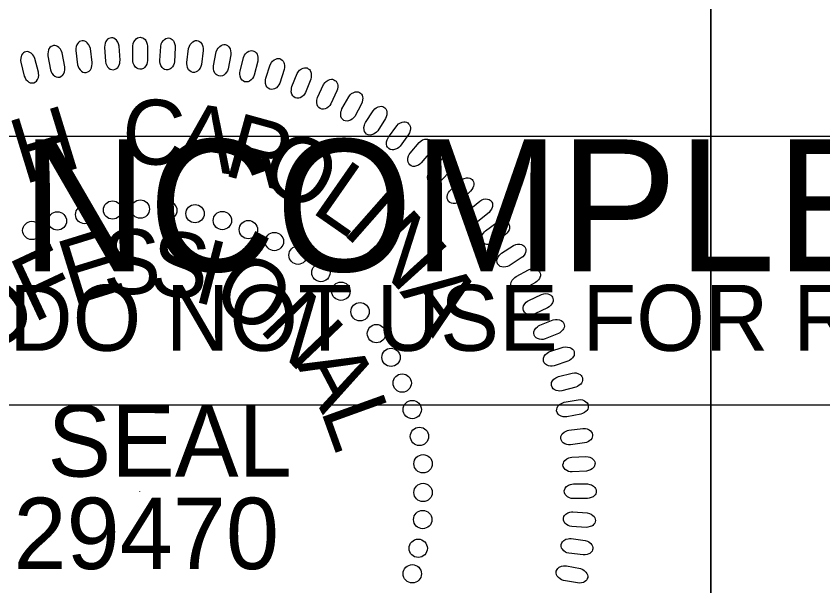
# Model space of a CAD drawing. Extents: x 497599 to 513368, y 404140 to 476034.
# Drawn here: x 507198 to 507268.5, y 439739.1 to 439788.9 of the extents above; entities that cross this region are included whole.
import ezdxf

# ---------------------------------------------------------------- set-up
doc = ezdxf.new("R2010")
doc.units = 0
for name, color, linetype in [('Sheet PE Seal Cell', 7, 'Continuous'), ('Sheet Profile CELL', 7, 'Continuous'), ('Sheet Sticker Incomplete CELL', 7, 'Continuous')]:
    doc.layers.add(name, color=color, linetype=linetype)

msp = doc.modelspace()

# ---------------------------------------------------------------- linework, layer by layer
at = {"layer": 'Sheet PE Seal Cell'}
msp.add_line((507208.804, 439747.402), (507208.804, 439747.355), dxfattribs=at)
for points in [[(507204.659, 439784.876), (507204.505, 439786.093), (507204.441, 439786.306), (507204.372, 439786.438), (507204.239, 439786.592), (507204.129, 439786.689), (507204.008, 439786.754), (507203.899, 439786.78), (507203.785, 439786.786), (507203.676, 439786.752), (507203.562, 439786.708), (507203.465, 439786.635), (507203.374, 439786.523), (507203.325, 439786.437), (507203.276, 439786.28), (507203.239, 439786.094), (507203.237, 439785.933), (507203.387, 439784.686), (507203.43, 439784.52), (507203.492, 439784.387), (507203.601, 439784.24), (507203.73, 439784.115), (507203.836, 439784.049), (507203.999, 439784.008), (507204.15, 439784.007), (507204.294, 439784.066), (507204.391, 439784.128), (507204.505, 439784.243), (507204.602, 439784.426), (507204.646, 439784.613), (507204.66, 439784.745)], [(507207.097, 439785.078), (507207.02, 439786.303), (507206.969, 439786.519), (507206.909, 439786.655), (507206.786, 439786.818), (507206.682, 439786.921), (507206.565, 439786.994), (507206.459, 439787.027), (507206.345, 439787.04), (507206.235, 439787.013), (507206.117, 439786.976), (507206.016, 439786.91), (507205.918, 439786.803), (507205.864, 439786.72), (507205.805, 439786.566), (507205.757, 439786.383), (507205.745, 439786.223), (507205.816, 439784.968), (507205.849, 439784.801), (507205.902, 439784.664), (507206.001, 439784.51), (507206.123, 439784.378), (507206.224, 439784.304), (507206.385, 439784.254), (507206.535, 439784.244), (507206.682, 439784.293), (507206.783, 439784.35), (507206.904, 439784.457), (507207.013, 439784.633), (507207.068, 439784.817), (507207.091, 439784.948)], [(507208.212, 439785.087), (507208.213, 439786.314), (507208.25, 439786.533), (507208.303, 439786.674), (507208.415, 439786.843), (507208.512, 439786.952), (507208.624, 439787.032), (507208.729, 439787.072), (507208.841, 439787.092), (507208.953, 439787.072), (507209.073, 439787.042), (507209.177, 439786.982), (507209.282, 439786.882), (507209.342, 439786.802), (507209.409, 439786.653), (507209.469, 439786.473), (507209.491, 439786.313), (507209.498, 439785.057), (507209.476, 439784.887), (507209.431, 439784.748), (507209.341, 439784.589), (507209.229, 439784.448), (507209.132, 439784.369), (507208.974, 439784.309), (507208.825, 439784.29), (507208.676, 439784.329), (507208.571, 439784.379), (507208.444, 439784.479), (507208.324, 439784.649), (507208.257, 439784.828), (507208.227, 439784.958)], [(507210.572, 439785.061), (507210.649, 439786.285), (507210.7, 439786.502), (507210.761, 439786.638), (507210.884, 439786.8), (507210.987, 439786.903), (507211.105, 439786.976), (507211.212, 439787.009), (507211.325, 439787.022), (507211.435, 439786.994), (507211.553, 439786.957), (507211.654, 439786.891), (507211.752, 439786.785), (507211.806, 439786.702), (507211.864, 439786.548), (507211.912, 439786.365), (507211.925, 439786.205), (507211.853, 439784.95), (507211.82, 439784.782), (507211.766, 439784.646), (507211.666, 439784.492), (507211.546, 439784.36), (507211.444, 439784.286), (507211.283, 439784.236), (507211.133, 439784.226), (507210.986, 439784.275), (507210.885, 439784.332), (507210.764, 439784.439), (507210.656, 439784.616), (507210.6, 439784.799), (507210.578, 439784.931)], [(507212.934, 439784.886), (507213.088, 439786.103), (507213.153, 439786.316), (507213.222, 439786.447), (507213.355, 439786.602), (507213.465, 439786.699), (507213.587, 439786.763), (507213.695, 439786.79), (507213.809, 439786.796), (507213.918, 439786.761), (507214.032, 439786.717), (507214.129, 439786.644), (507214.22, 439786.532), (507214.269, 439786.446), (507214.318, 439786.289), (507214.354, 439786.103), (507214.356, 439785.942), (507214.206, 439784.694), (507214.162, 439784.529), (507214.1, 439784.396), (507213.991, 439784.249), (507213.862, 439784.125), (507213.756, 439784.058), (507213.593, 439784.018), (507213.442, 439784.017), (507213.298, 439784.076), (507213.201, 439784.138), (507213.087, 439784.253), (507212.99, 439784.436), (507212.946, 439784.623), (507212.933, 439784.756)], [(507202.278, 439784.508), (507202.048, 439785.712), (507201.97, 439785.921), (507201.893, 439786.049), (507201.751, 439786.194), (507201.635, 439786.283), (507201.51, 439786.341), (507201.4, 439786.361), (507201.286, 439786.36), (507201.179, 439786.319), (507201.068, 439786.267), (507200.976, 439786.189), (507200.891, 439786.071), (507200.848, 439785.981), (507200.81, 439785.822), (507200.785, 439785.635), (507200.792, 439785.474), (507201.02, 439784.238), (507201.074, 439784.075), (507201.144, 439783.946), (507201.262, 439783.807), (507201.399, 439783.69), (507201.509, 439783.63), (507201.674, 439783.601), (507201.825, 439783.61), (507201.964, 439783.677), (507202.058, 439783.745), (507202.164, 439783.867), (507202.25, 439784.055), (507202.282, 439784.244), (507202.287, 439784.377)], [(507215.273, 439784.599), (507215.504, 439785.804), (507215.582, 439786.013), (507215.659, 439786.14), (507215.801, 439786.285), (507215.917, 439786.375), (507216.042, 439786.432), (507216.152, 439786.452), (507216.267, 439786.451), (507216.373, 439786.41), (507216.485, 439786.358), (507216.576, 439786.279), (507216.66, 439786.162), (507216.704, 439786.072), (507216.742, 439785.913), (507216.767, 439785.725), (507216.759, 439785.564), (507216.531, 439784.328), (507216.476, 439784.166), (507216.406, 439784.038), (507216.288, 439783.897), (507216.152, 439783.781), (507216.042, 439783.721), (507215.876, 439783.692), (507215.726, 439783.701), (507215.586, 439783.768), (507215.493, 439783.836), (507215.387, 439783.958), (507215.301, 439784.147), (507215.269, 439784.336), (507215.264, 439784.469)], [(507199.972, 439784.035), (507199.668, 439785.224), (507199.577, 439785.427), (507199.492, 439785.55), (507199.341, 439785.686), (507199.219, 439785.768), (507199.091, 439785.817), (507198.979, 439785.83), (507198.866, 439785.821), (507198.762, 439785.775), (507198.654, 439785.715), (507198.568, 439785.632), (507198.491, 439785.509), (507198.453, 439785.417), (507198.425, 439785.255), (507198.412, 439785.067), (507198.429, 439784.907), (507198.734, 439783.687), (507198.798, 439783.529), (507198.876, 439783.405), (507199.003, 439783.272), (507199.146, 439783.165), (507199.26, 439783.112), (507199.427, 439783.092), (507199.577, 439783.111), (507199.712, 439783.186), (507199.801, 439783.26), (507199.899, 439783.389), (507199.972, 439783.583), (507199.993, 439783.773), (507199.99, 439783.906)], [(507217.579, 439784.125), (507217.884, 439785.313), (507217.975, 439785.516), (507218.06, 439785.639), (507218.211, 439785.776), (507218.332, 439785.857), (507218.461, 439785.907), (507218.572, 439785.919), (507218.686, 439785.911), (507218.789, 439785.864), (507218.898, 439785.805), (507218.984, 439785.721), (507219.06, 439785.598), (507219.099, 439785.506), (507219.127, 439785.344), (507219.14, 439785.155), (507219.123, 439784.995), (507218.816, 439783.776), (507218.752, 439783.618), (507218.674, 439783.494), (507218.547, 439783.362), (507218.404, 439783.254), (507218.29, 439783.201), (507218.123, 439783.182), (507217.974, 439783.2), (507217.839, 439783.276), (507217.75, 439783.35), (507217.652, 439783.479), (507217.578, 439783.673), (507217.558, 439783.863), (507217.561, 439783.996)], [(507219.828, 439783.503), (507220.208, 439784.67), (507220.312, 439784.867), (507220.404, 439784.983), (507220.564, 439785.11), (507220.69, 439785.184), (507220.821, 439785.226), (507220.933, 439785.231), (507221.046, 439785.216), (507221.146, 439785.162), (507221.251, 439785.096), (507221.332, 439785.007), (507221.4, 439784.88), (507221.432, 439784.786), (507221.45, 439784.622), (507221.452, 439784.433), (507221.424, 439784.275), (507221.042, 439783.078), (507220.969, 439782.923), (507220.882, 439782.804), (507220.748, 439782.68), (507220.598, 439782.582), (507220.481, 439782.536), (507220.313, 439782.528), (507220.164, 439782.556), (507220.035, 439782.639), (507219.951, 439782.719), (507219.861, 439782.853), (507219.8, 439783.051), (507219.791, 439783.243), (507219.803, 439783.376)], [(507222.112, 439782.769), (507222.564, 439783.909), (507222.68, 439784.099), (507222.779, 439784.21), (507222.946, 439784.326), (507223.077, 439784.392), (507223.211, 439784.425), (507223.323, 439784.423), (507223.434, 439784.401), (507223.531, 439784.341), (507223.631, 439784.269), (507223.706, 439784.175), (507223.767, 439784.043), (507223.793, 439783.947), (507223.801, 439783.784), (507223.791, 439783.595), (507223.752, 439783.438), (507223.296, 439782.267), (507223.212, 439782.118), (507223.12, 439782.004), (507222.978, 439781.89), (507222.822, 439781.8), (507222.702, 439781.762), (507222.534, 439781.765), (507222.388, 439781.801), (507222.264, 439781.893), (507222.184, 439781.978), (507222.103, 439782.118), (507222.055, 439782.32), (507222.058, 439782.511), (507222.078, 439782.643)], [(507224.353, 439781.835), (507224.876, 439782.944), (507225.003, 439783.127), (507225.11, 439783.231), (507225.284, 439783.337), (507225.418, 439783.395), (507225.554, 439783.418), (507225.665, 439783.41), (507225.775, 439783.38), (507225.868, 439783.314), (507225.964, 439783.237), (507226.033, 439783.138), (507226.085, 439783.003), (507226.105, 439782.906), (507226.102, 439782.741), (507226.08, 439782.554), (507226.033, 439782.399), (507225.504, 439781.259), (507225.411, 439781.116), (507225.311, 439781.008), (507225.162, 439780.902), (507225.001, 439780.824), (507224.879, 439780.793), (507224.711, 439780.805), (507224.568, 439780.852), (507224.45, 439780.951), (507224.376, 439781.041), (507224.304, 439781.185), (507224.268, 439781.389), (507224.283, 439781.581), (507224.312, 439781.71)], [(507226.477, 439780.819), (507227.068, 439781.894), (507227.207, 439782.068), (507227.32, 439782.165), (507227.5, 439782.259), (507227.638, 439782.309), (507227.775, 439782.325), (507227.886, 439782.309), (507227.994, 439782.273), (507228.082, 439782.201), (507228.172, 439782.117), (507228.235, 439782.015), (507228.279, 439781.877), (507228.293, 439781.778), (507228.28, 439781.615), (507228.245, 439781.428), (507228.189, 439781.278), (507227.589, 439780.173), (507227.488, 439780.036), (507227.381, 439779.935), (507227.226, 439779.838), (507227.06, 439779.77), (507226.937, 439779.747), (507226.77, 439779.77), (507226.63, 439779.825), (507226.518, 439779.931), (507226.45, 439780.026), (507226.387, 439780.175), (507226.364, 439780.381), (507226.391, 439780.57), (507226.428, 439780.699)], [(507228.535, 439779.634), (507229.193, 439780.67), (507229.342, 439780.835), (507229.461, 439780.924), (507229.646, 439781.008), (507229.788, 439781.049), (507229.925, 439781.056), (507230.034, 439781.033), (507230.14, 439780.989), (507230.224, 439780.913), (507230.308, 439780.823), (507230.365, 439780.717), (507230.4, 439780.576), (507230.407, 439780.477), (507230.384, 439780.314), (507230.339, 439780.131), (507230.272, 439779.984), (507229.605, 439778.92), (507229.494, 439778.789), (507229.382, 439778.695), (507229.221, 439778.608), (507229.052, 439778.55), (507228.926, 439778.535), (507228.761, 439778.568), (507228.625, 439778.632), (507228.52, 439778.746), (507228.459, 439778.844), (507228.404, 439778.997), (507228.395, 439779.203), (507228.434, 439779.391), (507228.479, 439779.517)], [(507230.535, 439778.361), (507231.256, 439779.353), (507231.416, 439779.509), (507231.54, 439779.591), (507231.73, 439779.662), (507231.873, 439779.694), (507232.011, 439779.693), (507232.12, 439779.663), (507232.222, 439779.613), (507232.301, 439779.532), (507232.38, 439779.437), (507232.429, 439779.327), (507232.455, 439779.185), (507232.457, 439779.085), (507232.423, 439778.924), (507232.366, 439778.744), (507232.29, 439778.602), (507231.557, 439777.581), (507231.439, 439777.457), (507231.321, 439777.37), (507231.155, 439777.294), (507230.982, 439777.247), (507230.856, 439777.24), (507230.694, 439777.284), (507230.562, 439777.356), (507230.464, 439777.476), (507230.409, 439777.578), (507230.365, 439777.733), (507230.368, 439777.94), (507230.419, 439778.125), (507230.471, 439778.248)], [(507232.43, 439776.945), (507233.212, 439777.89), (507233.38, 439778.035), (507233.51, 439778.109), (507233.704, 439778.169), (507233.849, 439778.191), (507233.986, 439778.181), (507234.092, 439778.145), (507234.192, 439778.088), (507234.265, 439778.002), (507234.338, 439777.902), (507234.381, 439777.79), (507234.398, 439777.646), (507234.393, 439777.547), (507234.349, 439777.388), (507234.281, 439777.212), (507234.197, 439777.075), (507233.401, 439776.102), (507233.275, 439775.985), (507233.152, 439775.907), (507232.981, 439775.841), (507232.805, 439775.805), (507232.68, 439775.805), (507232.521, 439775.859), (507232.393, 439775.94), (507232.303, 439776.065), (507232.254, 439776.171), (507232.22, 439776.328), (507232.236, 439776.535), (507232.299, 439776.717), (507232.359, 439776.835)], [(507234.201, 439775.431), (507235.041, 439776.325), (507235.219, 439776.459), (507235.352, 439776.525), (507235.55, 439776.572), (507235.696, 439776.585), (507235.832, 439776.567), (507235.936, 439776.524), (507236.032, 439776.462), (507236.1, 439776.371), (507236.166, 439776.267), (507236.202, 439776.152), (507236.21, 439776.007), (507236.199, 439775.908), (507236.145, 439775.753), (507236.066, 439775.581), (507235.973, 439775.45), (507235.118, 439774.529), (507234.985, 439774.421), (507234.857, 439774.35), (507234.682, 439774.295), (507234.506, 439774.27), (507234.379, 439774.278), (507234.224, 439774.342), (507234.101, 439774.43), (507234.02, 439774.561), (507233.978, 439774.669), (507233.954, 439774.829), (507233.983, 439775.034), (507234.056, 439775.211), (507234.124, 439775.326)], [(507235.946, 439773.737), (507236.84, 439774.577), (507237.026, 439774.699), (507237.163, 439774.757), (507237.363, 439774.791), (507237.51, 439774.796), (507237.645, 439774.769), (507237.746, 439774.72), (507237.837, 439774.651), (507237.899, 439774.556), (507237.959, 439774.448), (507237.987, 439774.331), (507237.986, 439774.186), (507237.969, 439774.088), (507237.906, 439773.937), (507237.816, 439773.77), (507237.715, 439773.644), (507236.803, 439772.78), (507236.665, 439772.68), (507236.532, 439772.617), (507236.355, 439772.573), (507236.176, 439772.559), (507236.051, 439772.575), (507235.9, 439772.649), (507235.783, 439772.745), (507235.71, 439772.88), (507235.675, 439772.991), (507235.66, 439773.152), (507235.702, 439773.355), (507235.787, 439773.528), (507235.862, 439773.638)], [(507237.557, 439771.991), (507238.503, 439772.773), (507238.696, 439772.883), (507238.837, 439772.932), (507239.039, 439772.954), (507239.186, 439772.949), (507239.319, 439772.913), (507239.416, 439772.858), (507239.503, 439772.784), (507239.559, 439772.685), (507239.612, 439772.574), (507239.633, 439772.455), (507239.622, 439772.311), (507239.599, 439772.214), (507239.526, 439772.067), (507239.426, 439771.907), (507239.318, 439771.787), (507238.354, 439770.981), (507238.209, 439770.89), (507238.073, 439770.836), (507237.893, 439770.804), (507237.713, 439770.801), (507237.59, 439770.825), (507237.443, 439770.907), (507237.333, 439771.01), (507237.269, 439771.151), (507237.24, 439771.263), (507237.236, 439771.425), (507237.291, 439771.625), (507237.386, 439771.791), (507237.467, 439771.897)], [(507239.018, 439770.169), (507240.011, 439770.889), (507240.21, 439770.988), (507240.354, 439771.028), (507240.557, 439771.037), (507240.703, 439771.022), (507240.833, 439770.979), (507240.927, 439770.917), (507241.009, 439770.838), (507241.059, 439770.735), (507241.105, 439770.622), (507241.118, 439770.502), (507241.098, 439770.358), (507241.069, 439770.263), (507240.987, 439770.12), (507240.877, 439769.967), (507240.762, 439769.855), (507239.749, 439769.11), (507239.599, 439769.029), (507239.459, 439768.983), (507239.278, 439768.962), (507239.098, 439768.971), (507238.977, 439769.003), (507238.836, 439769.094), (507238.732, 439769.204), (507238.677, 439769.348), (507238.656, 439769.462), (507238.661, 439769.624), (507238.729, 439769.82), (507238.834, 439769.98), (507238.922, 439770.08)], [(507240.418, 439768.222), (507241.454, 439768.88), (507241.66, 439768.966), (507241.806, 439768.996), (507242.009, 439768.993), (507242.154, 439768.969), (507242.281, 439768.917), (507242.371, 439768.85), (507242.448, 439768.766), (507242.491, 439768.661), (507242.53, 439768.544), (507242.535, 439768.423), (507242.507, 439768.281), (507242.472, 439768.188), (507242.381, 439768.051), (507242.262, 439767.905), (507242.139, 439767.8), (507241.082, 439767.121), (507240.927, 439767.049), (507240.785, 439767.013), (507240.602, 439767.003), (507240.424, 439767.022), (507240.304, 439767.062), (507240.17, 439767.162), (507240.073, 439767.278), (507240.027, 439767.425), (507240.013, 439767.54), (507240.029, 439767.702), (507240.108, 439767.893), (507240.224, 439768.046), (507240.317, 439768.141)], [(507241.679, 439766.173), (507242.755, 439766.763), (507242.965, 439766.836), (507243.112, 439766.858), (507243.315, 439766.842), (507243.458, 439766.809), (507243.582, 439766.748), (507243.667, 439766.676), (507243.739, 439766.588), (507243.775, 439766.48), (507243.806, 439766.36), (507243.805, 439766.24), (507243.768, 439766.1), (507243.726, 439766.01), (507243.628, 439765.878), (507243.499, 439765.74), (507243.37, 439765.643), (507242.272, 439765.032), (507242.113, 439764.97), (507241.968, 439764.942), (507241.786, 439764.944), (507241.61, 439764.974), (507241.492, 439765.021), (507241.365, 439765.13), (507241.275, 439765.251), (507241.238, 439765.401), (507241.231, 439765.517), (507241.258, 439765.677), (507241.349, 439765.863), (507241.474, 439766.009), (507241.573, 439766.098)], [(507242.787, 439764.09), (507243.897, 439764.612), (507244.111, 439764.671), (507244.26, 439764.684), (507244.461, 439764.654), (507244.602, 439764.612), (507244.722, 439764.545), (507244.802, 439764.467), (507244.868, 439764.374), (507244.898, 439764.264), (507244.921, 439764.143), (507244.912, 439764.023), (507244.866, 439763.886), (507244.819, 439763.798), (507244.712, 439763.673), (507244.575, 439763.543), (507244.44, 439763.455), (507243.306, 439762.913), (507243.144, 439762.862), (507242.998, 439762.843), (507242.816, 439762.856), (507242.642, 439762.898), (507242.528, 439762.952), (507242.407, 439763.069), (507242.325, 439763.196), (507242.298, 439763.348), (507242.299, 439763.464), (507242.334, 439763.622), (507242.438, 439763.802), (507242.571, 439763.939), (507242.676, 439764.021)], [(507243.766, 439761.928), (507244.907, 439762.38), (507245.125, 439762.425), (507245.274, 439762.429), (507245.472, 439762.387), (507245.61, 439762.336), (507245.726, 439762.261), (507245.801, 439762.179), (507245.861, 439762.082), (507245.883, 439761.97), (507245.9, 439761.848), (507245.883, 439761.729), (507245.828, 439761.595), (507245.777, 439761.51), (507245.662, 439761.392), (507245.517, 439761.27), (507245.377, 439761.191), (507244.211, 439760.722), (507244.046, 439760.68), (507243.899, 439760.671), (507243.718, 439760.696), (507243.547, 439760.748), (507243.436, 439760.809), (507243.323, 439760.934), (507243.25, 439761.065), (507243.232, 439761.219), (507243.24, 439761.335), (507243.285, 439761.49), (507243.4, 439761.663), (507243.542, 439761.792), (507243.652, 439761.867)], [(507244.64, 439759.614), (507245.808, 439759.993), (507246.028, 439760.025), (507246.177, 439760.019), (507246.372, 439759.964), (507246.507, 439759.906), (507246.617, 439759.824), (507246.687, 439759.737), (507246.741, 439759.636), (507246.757, 439759.523), (507246.765, 439759.4), (507246.741, 439759.283), (507246.678, 439759.152), (507246.621, 439759.07), (507246.499, 439758.959), (507246.347, 439758.848), (507246.202, 439758.777), (507245.009, 439758.382), (507244.841, 439758.351), (507244.694, 439758.351), (507244.515, 439758.387), (507244.348, 439758.45), (507244.241, 439758.518), (507244.135, 439758.649), (507244.071, 439758.785), (507244.063, 439758.94), (507244.078, 439759.054), (507244.133, 439759.206), (507244.257, 439759.372), (507244.408, 439759.492), (507244.522, 439759.56)], [(507245.385, 439757.441), (507246.573, 439757.745), (507246.795, 439757.764), (507246.943, 439757.748), (507247.136, 439757.682), (507247.266, 439757.615), (507247.371, 439757.526), (507247.436, 439757.435), (507247.483, 439757.331), (507247.492, 439757.217), (507247.492, 439757.094), (507247.461, 439756.978), (507247.39, 439756.852), (507247.327, 439756.774), (507247.199, 439756.672), (507247.04, 439756.569), (507246.891, 439756.508), (507245.676, 439756.189), (507245.506, 439756.168), (507245.359, 439756.177), (507245.182, 439756.224), (507245.02, 439756.298), (507244.918, 439756.372), (507244.821, 439756.509), (507244.765, 439756.649), (507244.766, 439756.804), (507244.788, 439756.917), (507244.854, 439757.066), (507244.988, 439757.223), (507245.145, 439757.333), (507245.264, 439757.394)], [(507245.895, 439755.187), (507247.1, 439755.416), (507247.322, 439755.42), (507247.469, 439755.396), (507247.657, 439755.317), (507247.783, 439755.242), (507247.883, 439755.147), (507247.941, 439755.052), (507247.982, 439754.945), (507247.983, 439754.832), (507247.975, 439754.708), (507247.937, 439754.595), (507247.858, 439754.473), (507247.791, 439754.399), (507247.656, 439754.305), (507247.491, 439754.213), (507247.339, 439754.161), (507246.106, 439753.918), (507245.935, 439753.909), (507245.79, 439753.927), (507245.616, 439753.985), (507245.458, 439754.069), (507245.362, 439754.149), (507245.273, 439754.293), (507245.226, 439754.436), (507245.237, 439754.59), (507245.266, 439754.702), (507245.34, 439754.846), (507245.485, 439754.994), (507245.649, 439755.095), (507245.77, 439755.148)], [(507246.293, 439752.748), (507247.51, 439752.901), (507247.732, 439752.891), (507247.878, 439752.857), (507248.06, 439752.767), (507248.181, 439752.684), (507248.274, 439752.583), (507248.327, 439752.485), (507248.36, 439752.376), (507248.355, 439752.262), (507248.34, 439752.139), (507248.294, 439752.028), (507248.208, 439751.912), (507248.136, 439751.843), (507247.996, 439751.757), (507247.825, 439751.675), (507247.67, 439751.633), (507246.424, 439751.468), (507246.253, 439751.47), (507246.109, 439751.497), (507245.94, 439751.566), (507245.787, 439751.659), (507245.696, 439751.746), (507245.616, 439751.894), (507245.578, 439752.04), (507245.599, 439752.193), (507245.636, 439752.303), (507245.719, 439752.442), (507245.872, 439752.582), (507246.042, 439752.671), (507246.167, 439752.716)], [(507246.537, 439750.383), (507247.761, 439750.459), (507247.982, 439750.435), (507248.125, 439750.393), (507248.301, 439750.291), (507248.416, 439750.201), (507248.503, 439750.094), (507248.549, 439749.992), (507248.576, 439749.881), (507248.563, 439749.768), (507248.541, 439749.647), (507248.488, 439749.539), (507248.395, 439749.428), (507248.319, 439749.364), (507248.174, 439749.287), (507247.998, 439749.216), (507247.841, 439749.184), (507246.587, 439749.098), (507246.416, 439749.11), (507246.274, 439749.146), (507246.109, 439749.225), (507245.963, 439749.328), (507245.877, 439749.42), (507245.808, 439749.573), (507245.778, 439749.722), (507245.809, 439749.873), (507245.852, 439749.981), (507245.944, 439750.114), (507246.105, 439750.243), (507246.281, 439750.322), (507246.408, 439750.36)], [(507246.686, 439748.053), (507247.913, 439748.052), (507248.132, 439748.015), (507248.271, 439747.962), (507248.441, 439747.85), (507248.551, 439747.753), (507248.63, 439747.641), (507248.67, 439747.537), (507248.69, 439747.424), (507248.67, 439747.312), (507248.64, 439747.192), (507248.58, 439747.088), (507248.48, 439746.983), (507248.401, 439746.923), (507248.251, 439746.856), (507248.071, 439746.796), (507247.912, 439746.774), (507246.655, 439746.767), (507246.486, 439746.789), (507246.346, 439746.835), (507246.186, 439746.924), (507246.047, 439747.036), (507245.967, 439747.133), (507245.907, 439747.29), (507245.888, 439747.44), (507245.928, 439747.59), (507245.978, 439747.694), (507246.077, 439747.821), (507246.247, 439747.94), (507246.426, 439748.008), (507246.556, 439748.038)], [(507246.653, 439745.612), (507247.877, 439745.535), (507248.093, 439745.483), (507248.229, 439745.423), (507248.392, 439745.3), (507248.495, 439745.196), (507248.567, 439745.079), (507248.601, 439744.973), (507248.613, 439744.858), (507248.586, 439744.748), (507248.549, 439744.631), (507248.483, 439744.53), (507248.377, 439744.432), (507248.293, 439744.378), (507248.139, 439744.32), (507247.957, 439744.271), (507247.796, 439744.259), (507246.541, 439744.331), (507246.374, 439744.364), (507246.237, 439744.418), (507246.084, 439744.517), (507245.952, 439744.638), (507245.878, 439744.74), (507245.828, 439744.9), (507245.818, 439745.051), (507245.867, 439745.198), (507245.923, 439745.299), (507246.031, 439745.419), (507246.207, 439745.528), (507246.391, 439745.584), (507246.522, 439745.605)], [(507246.486, 439743.272), (507247.703, 439743.118), (507247.916, 439743.053), (507248.048, 439742.984), (507248.203, 439742.852), (507248.299, 439742.741), (507248.364, 439742.62), (507248.39, 439742.512), (507248.396, 439742.397), (507248.362, 439742.289), (507248.317, 439742.174), (507248.245, 439742.078), (507248.133, 439741.986), (507248.047, 439741.937), (507247.889, 439741.889), (507247.704, 439741.852), (507247.543, 439741.85), (507246.295, 439742.001), (507246.129, 439742.044), (507245.997, 439742.106), (507245.85, 439742.215), (507245.725, 439742.344), (507245.658, 439742.45), (507245.619, 439742.614), (507245.618, 439742.764), (507245.676, 439742.908), (507245.739, 439743.005), (507245.853, 439743.119), (507246.037, 439743.216), (507246.224, 439743.261), (507246.356, 439743.273)], [(507246.089, 439740.885), (507247.294, 439740.654), (507247.502, 439740.577), (507247.63, 439740.5), (507247.776, 439740.357), (507247.865, 439740.241), (507247.922, 439740.116), (507247.942, 439740.006), (507247.94, 439739.892), (507247.9, 439739.786), (507247.848, 439739.674), (507247.769, 439739.582), (507247.651, 439739.499), (507247.562, 439739.454), (507247.403, 439739.416), (507247.215, 439739.391), (507247.054, 439739.399), (507245.819, 439739.628), (507245.656, 439739.682), (507245.528, 439739.752), (507245.388, 439739.87), (507245.271, 439740.006), (507245.211, 439740.117), (507245.182, 439740.282), (507245.191, 439740.433), (507245.258, 439740.572), (507245.326, 439740.666), (507245.448, 439740.772), (507245.637, 439740.857), (507245.827, 439740.89), (507245.959, 439740.894)]]:
    msp.add_lwpolyline(points, close=True, dxfattribs=at)
for centre in [(507206.441, 439771.992), (507208.869, 439772.071), (507211.258, 439771.95), (507204.012, 439771.594), (507213.647, 439771.671), (507216.035, 439771.072), (507201.623, 439771.037), (507199.393, 439770.201), (507218.304, 439770.275), (507220.573, 439769.238), (507222.643, 439768.043), (507224.634, 439766.528), (507226.385, 439764.894), (507228.056, 439763.101), (507229.489, 439761.188), (507230.762, 439759.116), (507231.735, 439756.867), (507232.61, 439754.556), (507233.246, 439752.206), (507233.564, 439749.815), (507233.563, 439747.306), (507233.533, 439744.942), (507233.134, 439742.432), (507232.616, 439740.201)]:
    msp.add_circle(centre, 0.801, dxfattribs=at)
at = {"layer": 'Sheet Profile CELL'}
msp.add_line((507258.678, 439811.094), (507258.678, 439698.644), dxfattribs=at)
for points in [[(507158.628, 439811.094), (507258.678, 439811.094), (507258.678, 439698.594), (507158.628, 439698.594)], [(507258.678, 439811.094), (507358.678, 439811.094), (507358.678, 439698.594), (507258.678, 439698.594)]]:
    msp.add_lwpolyline(points, close=True, dxfattribs=at)
at = {"layer": 'Sheet Sticker Incomplete CELL'}
msp.add_lwpolyline([(507185.195, 439754.938), (507185.195, 439778.438), (507332.195, 439778.438), (507332.195, 439754.938)], close=True, dxfattribs=at)

# ---------------------------------------------------------------- texts
at = {"layer": 'Sheet PE Seal Cell'}
for s, height, rotation, p in [('C', 5.669, 357.58768, (507207.187, 439776.082)), ('H', 5.669, 17.05575, (507198.682, 439774.198)), ('A', 5.669, 351.09832, (507211.763, 439775.874)), ('R', 5.669, 344.60896, (507215.969, 439775.079)), ('O', 5.669, 331.63025, (507218.924, 439774.425)), ('L', 5.669, 325.14089, (507223.657, 439771.894)), ('I', 5.669, 318.65154, (507226.35, 439770.041)), ('N', 5.669, 312.16218, (507228.155, 439768.621)), ('E', 5.669, 17.16862, (507202.878, 439763.629)), ('S', 5.669, 1.28903, (507205.646, 439764.589)), ('S', 5.669, 353.34923, (507209.506, 439764.69)), ('F', 5.669, 25.10842, (507199.488, 439762.091)), ('I', 5.669, 345.40944, (507213.307, 439764.059)), ('O', 5.669, 329.52984, (507214.81, 439763.887)), ('A', 5.669, 305.67282, (507231.475, 439764.841)), ('O', 5.669, 40.98802, (507195.791, 439758.952)), ('N', 5.669, 313.65025, (507219.122, 439761.583)), ('A', 5.669, 297.77065, (507222.459, 439758.502)), ('L', 5.669, 289.83086, (507224.583, 439754.507)), ('SEAL', 6.2363, 359.98136, (507200.762, 439748.695)), ('29470', 6.2363, 359.98136, (507197.791, 439740.617))]:
    msp.add_text(s, height=height, rotation=rotation, dxfattribs=at).set_placement(p)
at = {"layer": 'Sheet Sticker Incomplete CELL'}
for s, height, p in [('INCOMPLETE PLANS', 11.52, (507194.145, 439766.638)), ('DO NOT USE FOR R/W ACQUISITION', 5.76, (507197.395, 439759.688))]:
    msp.add_text(s, height=height, dxfattribs=at).set_placement(p)

doc.saveas('drawing.dxf')
